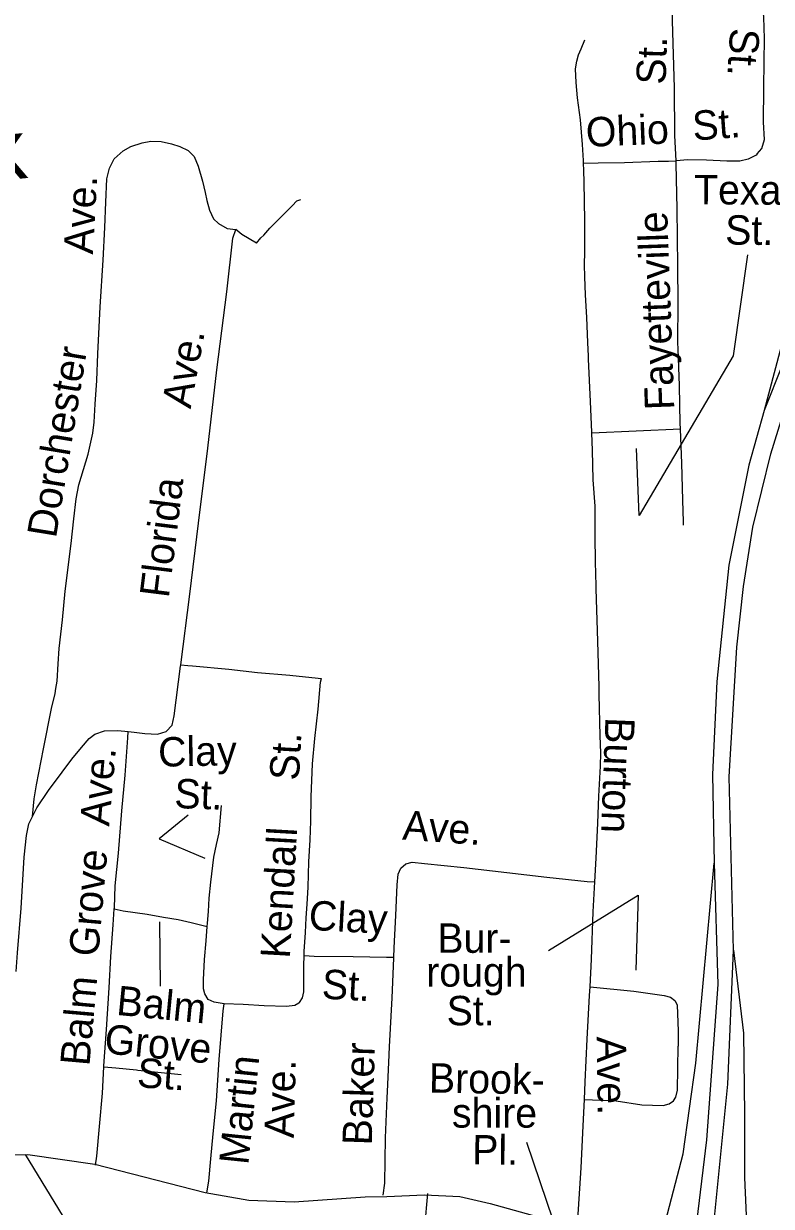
# Model space of a CAD drawing. Extents: x 925297 to 940193, y 663541 to 689899.
# Drawn here: x 928734 to 929116, y 688127 to 688730 of the extents above; entities that cross this region are included whole.
import ezdxf

# ---------------------------------------------------------------- set-up
doc = ezdxf.new("R2010")
doc.units = 0
doc.layers.add('Default', color=7, linetype='Continuous')
doc.layers.add('Old_Level_28', color=7, linetype='Continuous')

msp = doc.modelspace()

# ---------------------------------------------------------------- linework, layer by layer
at = {"layer": 'Default'}
msp.add_line((929069.73, 688523.26), (929024.41, 688521.14), dxfattribs=at)
for points in [[(929240.68, 688799), (929227.23, 688772.53), (929180.84, 688684.11), (929164.1, 688653.95), (929138.06, 688598.39), (929121.88, 688556.31), (929112.47, 688532.84)], [(929108.94, 688663.7), (929111.3, 688666.43), (929112.62, 688671.03), (929112.14, 688679.96), (929112.31, 688697.45), (929112.37, 688710.68), (929112.61, 688722.6), (929112.33, 688733.46), (929111.33, 688742.29), (929109.75, 688747.64), (929106.64, 688751.17), (929103.33, 688752.74), (929096.45, 688754.02), (929090.6, 688754.27), (929084.08, 688754.39), (929078.13, 688754.15), (929073.55, 688753.81), (929070.57, 688753.47), (929068.16, 688752.56), (929066.69, 688750.55), (929066.4, 688749.72)], [(929067.48, 688660.24), (929066.83, 688673.17), (929066.61, 688697.45), (929065.93, 688719.98), (929065.44, 688737.47), (929065.4, 688742.58), (929065.6, 688747.42), (929066.4, 688749.72)], [(929020.25, 688658.91), (929020.21, 688660.27), (929019.71, 688668.55), (929018.62, 688681.13), (929017.2, 688692.37), (929016.51, 688700.08), (929016.07, 688707.08), (929016.71, 688710.95), (929017.67, 688714.31), (929018.97, 688717.27), (929020.85, 688721.91)], [(929096.73, 688257.47), (929094.63, 688345.9), (929098.42, 688411.96), (929101.91, 688442.91), (929106.59, 688473.2), (929115.78, 688510.69), (929130.1, 688556.83), (929161.64, 688630.45), (929178.69, 688663.27), (929197.77, 688696.08)], [(929170.37, 688686.19), (929161.35, 688668.03), (929152.39, 688648.51), (929140.25, 688618.43), (929132.28, 688599.71), (929123.36, 688573.77), (929112.47, 688532.84)], [(928750.82, 688390.83), (928751.37, 688394.6), (928752.02, 688403.51), (928752.54, 688411.38), (928754.12, 688425.97), (928755.6, 688440.54), (928758.53, 688464.9), (928759.97, 688477.46), (928761.2, 688487.64), (928762.5, 688494.82), (928767.19, 688510.56), (928769.65, 688521.27), (928770.29, 688526.73), (928770.92, 688535.93), (928771.68, 688548.06), (928772.22, 688561.65), (928773.34, 688585.7), (928774.86, 688609.44), (928775.7, 688626.08), (928776.32, 688638.99), (928776.8, 688650.98), (928778.13, 688656.4), (928780.61, 688661.11), (928785.12, 688665.32), (928789.01, 688667.56), (928794.89, 688669.35), (928799.27, 688670.16), (928804.62, 688669.99), (928809.74, 688668.82), (928814.14, 688667.47), (928818.25, 688665.41), (928821.34, 688662.35), (928823.42, 688657.47), (928825.63, 688649.76), (928826.99, 688644.06), (928827.82, 688639.91), (928829.28, 688635.04), (928831.21, 688630.55), (928833.78, 688628.27), (928838.29, 688625.7), (928842.62, 688625.16)], [(929108.94, 688663.7), (929108.37, 688663.04), (929104.35, 688661), (929100.09, 688659.99), (929093.29, 688659.97), (929082.92, 688660.42), (929073.41, 688660.63), (929067.48, 688660.24)], [(929020.25, 688658.91), (929027.6, 688659.06), (929041.08, 688659.25), (929058.37, 688659.96), (929063.6, 688659.98), (929067.48, 688660.24)], [(929024.41, 688521.14), (929024.4, 688521.4), (929024.38, 688521.79), (929023.69, 688537.34), (929022.81, 688558.98), (929022.73, 688560.55), (929022.41, 688567.45), (929021.88, 688580.14), (929021.25, 688591.75), (929020.8, 688600.92), (929020.69, 688607.04), (929020.88, 688613.71), (929020.85, 688629.74), (929020.55, 688649.3), (929020.37, 688655.18), (929020.25, 688658.91)], [(929069.73, 688523.26), (929069.71, 688523.6), (929069.61, 688526.16), (929069.15, 688545.44), (929068.48, 688564.04), (929068.35, 688567.5), (929068.59, 688587.94), (929068.39, 688606.37), (929067.93, 688635.59), (929067.56, 688658.67), (929067.48, 688660.24)], [(928853.27, 688618.09), (928855.38, 688620.82), (928856.94, 688622.28), (928860.08, 688625.72), (928864.55, 688630.41), (928871.41, 688637.27), (928873.85, 688639.82), (928875.93, 688640.38)], [(928814.51, 688402.96), (928819.14, 688439.05), (928823.67, 688475.31), (928828.32, 688513.51), (928832.99, 688553.59), (928838.04, 688593.31), (928841.18, 688620.73), (928842.62, 688625.16)], [(928853.27, 688618.09), (928845.76, 688622.49), (928842.62, 688625.16)], [(929103.89, 688612.24), (929096.62, 688560.61), (929048.65, 688479.16), (929047.2, 688513.34)], [(929112.47, 688532.84), (929104.65, 688504.85), (929094.47, 688453.83), (929088.24, 688394.41), (929086, 688347.1), (929086.89, 688301.8)], [(929026.58, 688443.32), (929026.39, 688455.51), (929026.13, 688468.66), (929026.07, 688483.92), (929025.19, 688497.38), (929024.75, 688512.56), (929024.41, 688521.14)], [(929071.18, 688474.32), (929071.32, 688475.98), (929070.97, 688486.93), (929070.43, 688505.97), (929069.73, 688523.26)], [(929028.11, 688391.83), (929027.5, 688415.03), (929026.6, 688441.82), (929026.58, 688443.32)], [(928787.65, 688368.9), (928790.79, 688368.61), (928796.25, 688367.88), (928802.61, 688367.59), (928807.14, 688369), (928810.11, 688372.25), (928811.17, 688376.95), (928814.42, 688402.26), (928814.51, 688402.96)], [(928814.51, 688402.96), (928818.12, 688402.67), (928820.62, 688402.54), (928839.06, 688400.85), (928853.68, 688399.04), (928870.23, 688397.68), (928881.5, 688396.5), (928886.45, 688396.06)], [(928877.55, 688254.41), (928877.6, 688256.66), (928878.32, 688266.44), (928878.53, 688273.95), (928879.01, 688280.82), (928879.61, 688289.59), (928879.97, 688302.41), (928880.62, 688313.72), (928880.89, 688323.15), (928881.11, 688335.69), (928881.8, 688352.51), (928882.95, 688365.36), (928884.75, 688380.42), (928885.88, 688394.1), (928886.45, 688396.06)], [(928738.85, 688325.58), (928739.74, 688334.6), (928740.81, 688341.7), (928744.54, 688360.18), (928748.48, 688380.73), (928750.47, 688388.39), (928750.82, 688390.83)], [(929025.95, 688292.27), (929026.66, 688304.35), (929027.46, 688322.26), (929028.1, 688335.95), (929028.85, 688351.21), (929029.12, 688358.07), (929028.75, 688366.82), (929028.21, 688387.9), (929028.11, 688391.83)], [(928738.85, 688325.58), (928741.02, 688330.06), (928747.1, 688338.92), (928753.96, 688348.2), (928758.96, 688354.79), (928763.81, 688360.72), (928767.75, 688365.37), (928770.69, 688367.67), (928775.57, 688369.3), (928782.35, 688369.4), (928787.65, 688368.9)], [(928780.62, 688278.44), (928780.67, 688279.05), (928781.12, 688290.27), (928782.72, 688306.89), (928784.43, 688328.55), (928786.12, 688346.73), (928787.49, 688365.71), (928787.65, 688368.9)], [(928818.38, 688326.26), (928803.55, 688314.25), (928826.86, 688304.35)], [(928828.06, 688269.38), (928828.2, 688271.12), (928828.69, 688277.16), (928829.05, 688283.96), (928829.96, 688292.13), (928831.45, 688304.77), (928832.84, 688311.25), (928834.1, 688317.32), (928835.41, 688331.26)], [(928730.46, 688246.45), (928731.13, 688256.06), (928732.98, 688278.79), (928734.58, 688304.9), (928735.76, 688315.85), (928737.04, 688321.84), (928738.85, 688325.58)], [(928923.38, 688253.7), (928923.59, 688258.52), (928924.44, 688275.09), (928925.01, 688290.64), (928925.48, 688296.23), (928926.84, 688299.16), (928929.4, 688301.49), (928932.64, 688302.29), (928939.07, 688301.69), (928959.02, 688299.53), (928981.03, 688297.02), (929001.45, 688294.65), (929022.07, 688292.44), (929025.95, 688292.27)], [(929056.23, 688091.33), (929060.16, 688111.77), (929071.16, 688153.44), (929077.5, 688199.74), (929086.89, 688301.8)], [(929086.89, 688301.8), (929088.81, 688239.92), (929082.95, 688160.52), (929073.52, 688081.89)], [(929023.53, 688238.66), (929024.2, 688252.83), (929025.05, 688276.94), (929025.95, 688292.27)], [(929002.32, 688257.24), (929048.1, 688285.43), (929046.93, 688247.25)], [(928775.19, 688197.86), (928775.21, 688198.31), (928776.65, 688216.96), (928778.02, 688238.25), (928778.81, 688254.11), (928780.01, 688270.38), (928780.62, 688278.44)], [(928780.62, 688278.44), (928785.15, 688277.52), (928797.37, 688275.82), (928805.75, 688274.18), (928813.29, 688272.95), (928819.87, 688271.45), (928825.94, 688269.96), (928828.06, 688269.38)], [(928804.27, 688239.07), (928803.89, 688271.91)], [(928836.65, 688230.06), (928831.55, 688230.79), (928828.6, 688232.15), (928826.82, 688235.12), (928826.14, 688237.65), (928826.18, 688242.25), (928826.62, 688252.55), (928827.47, 688262.17), (928828.06, 688269.38)], [(928874.78, 688230.42), (928875.19, 688230.71), (928876.73, 688233.05), (928877.39, 688236.09), (928877.45, 688241.37), (928877.43, 688249.51), (928877.55, 688254.41)], [(928923.38, 688253.7), (928919.56, 688253.7), (928902.63, 688254), (928882.69, 688254.19), (928877.55, 688254.41)], [(928917.98, 688132.31), (928918.69, 688138.48), (928919.01, 688161.61), (928920.01, 688182.1), (928920.16, 688185.23), (928920.84, 688200.15), (928921.2, 688208.12), (928922.46, 688233.03), (928923.36, 688253.24), (928923.38, 688253.7)], [(929082.59, 688077.51), (929084.16, 688092.08), (929093.9, 688188.99), (929096.73, 688257.47)], [(929096.73, 688257.47), (929101.82, 688215.02), (929102.38, 688173.71), (929102.38, 688141.45), (929103.51, 688114.29), (929105.78, 688088.26), (929106.34, 688070.15)], [(929020.63, 688181.27), (929021.01, 688190.27), (929022.13, 688212.03), (929023.32, 688234.18), (929023.53, 688238.66)], [(929023.53, 688238.66), (929045.88, 688236.54), (929061.35, 688234.29), (929064.54, 688233.35), (929066.88, 688231.73), (929067.99, 688229.49), (929068.54, 688216.12), (929068.44, 688208.32)], [(928827.79, 688133.64), (928828.83, 688139.53), (928829.89, 688150.94), (928831.05, 688163.7), (928832.86, 688180.49), (928834.23, 688201.54), (928836.17, 688226.37), (928836.65, 688230.06)], [(928874.78, 688230.42), (928872.86, 688229.09), (928868.62, 688228.61), (928857.13, 688229.01), (928846.36, 688229.68), (928836.65, 688230.06)], [(929020.63, 688181.27), (929036.82, 688180.43), (929049.94, 688178.53), (929060.92, 688178.2), (929063.9, 688178.93), (929066.08, 688180.5), (929067.4, 688182.3), (929068.18, 688185.89), (929068.44, 688208.32)], [(928770.98, 688147.72), (928771.75, 688152.21), (928773, 688167.37), (928774.58, 688184.4), (928775.19, 688197.86)], [(928775.19, 688197.86), (928781.36, 688197.28), (928791.93, 688196.27), (928792.6, 688196.2), (928814.8, 688193.95)], [(929016.43, 688114.05), (929017.33, 688120.02), (929019.04, 688146.27), (929020.05, 688167.74), (929020.63, 688181.27)], [(928991.04, 688159.4), (929011.34, 688099.72), (929029.63, 688075.6)], [(928735.17, 688153.15), (928756.36, 688118.27), (928770.74, 688097.06)], [(928940.46, 688133.27), (928939.85, 688125.68), (928937.93, 688103.26), (928936.69, 688088.34), (928935.85, 688078.14), (928933.55, 688056.14), (928931.36, 688026.41), (928928.28, 687996), (928927.96, 687991.82)]]:
    msp.add_lwpolyline(points, dxfattribs=at)
at = {"layer": 'Old_Level_28'}
msp.add_lwpolyline([(928639.49, 688117.35), (928654.87, 688130.19), (928667.72, 688136.23), (928688.3, 688144.9), (928703.27, 688148.91), (928717.66, 688152.47), (928725.18, 688152.94), (928736.48, 688153.09), (928770.68, 688148.21), (928827.03, 688133.76), (928849.33, 688129.77), (928872.49, 688128.91), (928908.64, 688131.6), (928919.8, 688131.64), (928939.04, 688132.57), (928957.06, 688131.75), (928972.56, 688128.16), (928997.1, 688121.24), (929012.71, 688116.14), (929028.65, 688108.55), (929037.28, 688102.7), (929050.12, 688094.96), (929057.7, 688090.16), (929073.52, 688081.89)], dxfattribs=at)

# ---------------------------------------------------------------- texts
at = {"layer": 'Default'}
for s, height, rotation, p in [('St.', 15, 266.48918, (929095.17, 688728.16)), ('St.', 15, 88.25275, (929062.1, 688698.91)), ('Ohio', 15, 2.4116, (929021.69, 688667.26)), ('St.', 15, 4.22232, (929076.32, 688670.5)), ('Creek', 30, 5.85786, (928630.17, 688640.53)), ('Texas', 15, 359.64196, (929076.61, 688638.02)), ('Ave.', 15, 86.81644, (928769.71, 688612.25)), ('Fayetteville', 15, 92.06683, (929066.58, 688533.23)), ('St.', 15, 359.41414, (929092.49, 688617.46)), ('Ave.', 15, 79.51406, (928819.58, 688533.31)), ('Dorchester', 15, 80.61916, (928750.81, 688467.26)), ('Florida', 15, 82.90116, (928808.39, 688436.75)), ('Burton', 15, 267.82959, (929031.42, 688376.44)), ('Clay', 15, 1.09844, (928803.13, 688350.99)), ('St.', 15, 86.7622, (928874.82, 688343.72)), ('Ave.', 15, 84.96833, (928777.98, 688320.36)), ('St.', 15, 357.89102, (928811.12, 688329.95)), ('Ave.', 15, 355.97719, (928927.45, 688313.84)), ('Kendall', 15, 86.7622, (928870.23, 688252.89)), ('Grove', 15, 84.96833, (928772.36, 688253.78)), ('Clay', 15, 356.90681, (928879.64, 688267.79)), ('St.', 15, 356.90681, (928886.31, 688232.69)), ('Balm', 15, 84.93927, (928767.9, 688197.96)), ('Balm', 15, 354.41216, (928781.31, 688224.41)), ('Grove', 15, 354.41216, (928775.12, 688204.81)), ('Ave.', 15, 270.83365, (929026.88, 688213.31)), ('Baker', 15, 88.12695, (928912.05, 688157.64)), ('St.', 15, 356.07758, (928791.95, 688187.5)), ('Martin', 15, 84.16129, (928849.01, 688147.5)), ('Ave.', 15, 88.45324, (928872.26, 688161.32)), ('Brook-', 15, 358.9871, (928941.17, 688184.76)), ('shire', 15, 359.95022, (928953.01, 688166.85)), ('Pl.', 15, 359.45049, (928963.29, 688148.08))]:
    msp.add_text(s, height=height, rotation=rotation, dxfattribs=at).set_placement(p)
for s, p in [('Bur-', (928945.54, 688256.04)), ('rough', (928939.86, 688238.78)), ('St.', (928950.32, 688219.05))]:
    msp.add_text(s, height=15, dxfattribs=at).set_placement(p)

doc.saveas('drawing.dxf')
